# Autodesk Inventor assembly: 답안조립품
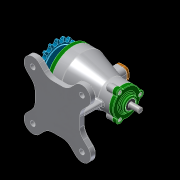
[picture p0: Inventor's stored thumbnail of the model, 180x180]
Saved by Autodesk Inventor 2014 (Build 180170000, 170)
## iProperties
Created: 2018-03
Part Number: 답안조립품
Document SubType Name: Assembly
Designer: user
Author: user
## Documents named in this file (15)
- C:\Users\user\Desktop\480307V1007\답안조립품.iam
- C:\Users\user\Desktop\480307V1007\뒤커버.ipt
- C:\Users\user\Desktop\480307V1007\마개.ipt
- C:\Users\user\Desktop\480307V1007\베어링-6200.ipt
- C:\Users\user\Desktop\480307V1007\베어링-6203.ipt
- C:\Users\user\Desktop\480307V1007\본체.ipt
- C:\Users\user\Desktop\480307V1007\볼트 M4 x 12.ipt
- 볼트 M4 x 12.ipt
- C:\Users\user\Desktop\480307V1007\스프로킷.ipt
- C:\Users\user\Desktop\480307V1007\앞커버.ipt
- C:\Users\user\Desktop\480307V1007\오일 실 10 20 7.ipt
- C:\Users\user\Desktop\480307V1007\오일 실 17 30 8.ipt
- C:\Users\user\Desktop\480307V1007\축.ipt
- C:\Users\user\Desktop\480307V1007\키 5 x 5.ipt
- 키 5 x 5.ipt
